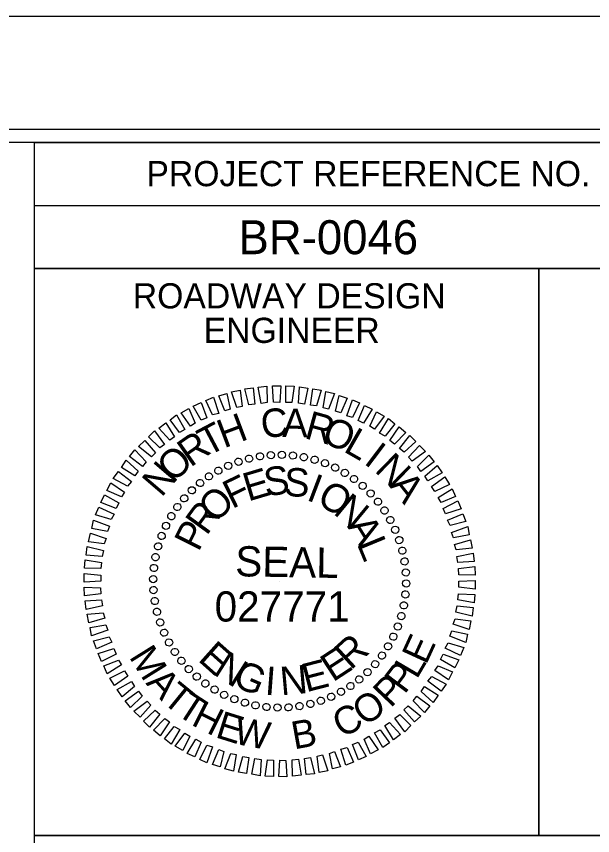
# Model space of a CAD drawing. Extents: x 1497225 to 1499181, y 579958 to 582278.
# Drawn here: x 1498688.6 to 1498802.9, y 582115.4 to 582278 of the extents above; entities that cross this region are included whole.
import ezdxf

# ---------------------------------------------------------------- set-up
doc = ezdxf.new("R2010")
doc.units = 0
for name, color, linetype in [('Sheet Cutting Line CELL', 7, 'Continuous'), ('Sheet Data Field CELL', 7, 'Continuous'), ('Sheet Plot Border Inside CELL', 7, 'Continuous'), ('Sheet Plot Border Outside CELL', 7, 'Continuous'), ('Sheet Professional Seal CELL', 7, 'Continuous'), ('Sheet Sticker Exception Certification CELL', 7, 'Continuous'), ('Sheet Typical CELL', 7, 'Continuous')]:
    doc.layers.add(name, color=color, linetype=linetype)

msp = doc.modelspace()

# ---------------------------------------------------------------- linework, layer by layer
at = {"layer": 'Sheet Cutting Line CELL'}
msp.add_line((1498909.23, 582277.96), (1497225.23, 582277.96), dxfattribs=at)
at = {"layer": 'Sheet Plot Border Inside CELL'}
msp.add_lwpolyline([(1498904.73, 582255.51), (1497238.23, 582255.51), (1497238.23, 581200.41), (1498904.73, 581200.41)], close=True, dxfattribs=at)
at = {"layer": 'Sheet Plot Border Outside CELL'}
msp.add_lwpolyline([(1498909.23, 582277.96), (1497225.23, 582277.96), (1497225.23, 581177.96), (1498909.23, 581177.96)], close=True, dxfattribs=at)
at = {"layer": 'Sheet Professional Seal CELL'}
for p, q in [((1498736.91, 582190.62), (1498736.91, 582190.62)), ((1498739.06, 582190.92), (1498739.06, 582190.92)), ((1498741.26, 582190.97), (1498741.26, 582190.97)), ((1498743.46, 582190.82), (1498743.46, 582190.82)), ((1498745.61, 582190.47), (1498745.61, 582190.47)), ((1498730.61, 582188.82), (1498730.61, 582188.82)), ((1498732.61, 582189.62), (1498732.61, 582189.62)), ((1498734.71, 582190.22), (1498734.71, 582190.22)), ((1498747.71, 582190.02), (1498747.71, 582190.02)), ((1498749.81, 582189.32), (1498749.81, 582189.32)), ((1498728.66, 582187.82), (1498728.66, 582187.82)), ((1498751.81, 582188.42), (1498751.81, 582188.42)), ((1498753.76, 582187.42), (1498753.76, 582187.42)), ((1498726.76, 582186.67), (1498726.76, 582186.67)), ((1498755.56, 582186.17), (1498755.56, 582186.17)), ((1498723.36, 582183.92), (1498723.36, 582183.92)), ((1498725.01, 582185.42), (1498725.01, 582185.42)), ((1498757.31, 582184.82), (1498757.31, 582184.82)), ((1498721.86, 582182.37), (1498721.86, 582182.37)), ((1498758.86, 582183.32), (1498758.86, 582183.32)), ((1498720.51, 582180.62), (1498720.51, 582180.62)), ((1498760.36, 582181.67), (1498760.36, 582181.67)), ((1498761.61, 582179.92), (1498761.61, 582179.92)), ((1498719.26, 582178.82), (1498719.26, 582178.82)), ((1498762.76, 582178.02), (1498762.76, 582178.02)), ((1498718.26, 582176.87), (1498718.26, 582176.87)), ((1498763.76, 582176.07), (1498763.76, 582176.07)), ((1498717.36, 582174.87), (1498717.36, 582174.87)), ((1498716.66, 582172.77), (1498716.66, 582172.77)), ((1498764.56, 582174.07), (1498764.56, 582174.07)), ((1498765.16, 582171.97), (1498765.16, 582171.97)), ((1498716.21, 582170.67), (1498716.21, 582170.67)), ((1498765.56, 582169.77), (1498765.56, 582169.77)), ((1498715.86, 582168.52), (1498715.86, 582168.52)), ((1498765.86, 582167.62), (1498765.86, 582167.62)), ((1498715.71, 582166.32), (1498715.71, 582166.32)), ((1498740.81, 582165.87), (1498740.81, 582165.87)), ((1498765.91, 582165.42), (1498765.91, 582165.42)), ((1498715.76, 582164.12), (1498715.76, 582164.12)), ((1498765.76, 582163.22), (1498765.76, 582163.22)), ((1498716.06, 582161.97), (1498716.06, 582161.97)), ((1498765.41, 582161.07), (1498765.41, 582161.07)), ((1498716.46, 582159.77), (1498716.46, 582159.77)), ((1498764.96, 582158.97), (1498764.96, 582158.97)), ((1498717.06, 582157.67), (1498717.06, 582157.67)), ((1498764.26, 582156.87), (1498764.26, 582156.87)), ((1498717.86, 582155.67), (1498717.86, 582155.67)), ((1498763.36, 582154.87), (1498763.36, 582154.87)), ((1498718.86, 582153.72), (1498718.86, 582153.72)), ((1498720.01, 582151.82), (1498720.01, 582151.82)), ((1498762.36, 582152.92), (1498762.36, 582152.92)), ((1498721.26, 582150.07), (1498721.26, 582150.07)), ((1498761.11, 582151.12), (1498761.11, 582151.12)), ((1498722.76, 582148.42), (1498722.76, 582148.42)), ((1498759.76, 582149.37), (1498759.76, 582149.37)), ((1498724.31, 582146.92), (1498724.31, 582146.92)), ((1498758.26, 582147.82), (1498758.26, 582147.82)), ((1498726.06, 582145.57), (1498726.06, 582145.57)), ((1498754.86, 582145.07), (1498754.86, 582145.07)), ((1498756.61, 582146.32), (1498756.61, 582146.32)), ((1498727.86, 582144.32), (1498727.86, 582144.32)), ((1498729.81, 582143.32), (1498729.81, 582143.32)), ((1498752.96, 582143.92), (1498752.96, 582143.92)), ((1498731.81, 582142.42), (1498731.81, 582142.42)), ((1498733.91, 582141.72), (1498733.91, 582141.72)), ((1498749.01, 582142.12), (1498749.01, 582142.12)), ((1498751.01, 582142.92), (1498751.01, 582142.92)), ((1498736.01, 582141.27), (1498736.01, 582141.27)), ((1498738.16, 582140.92), (1498738.16, 582140.92)), ((1498740.36, 582140.77), (1498740.36, 582140.77)), ((1498742.56, 582140.82), (1498742.56, 582140.82)), ((1498744.71, 582141.12), (1498744.71, 582141.12)), ((1498746.91, 582141.52), (1498746.91, 582141.52))]:
    msp.add_line(p, q, dxfattribs=at)
for points in [[(1498732.31, 582200.32), (1498731.26, 582203.47), (1498732.96, 582203.82), (1498733.36, 582200.57)], [(1498734.71, 582200.87), (1498733.91, 582204.07), (1498735.56, 582204.22), (1498735.91, 582201.02)], [(1498737.11, 582201.17), (1498736.56, 582204.37), (1498738.26, 582204.57), (1498738.31, 582201.32)], [(1498739.61, 582201.42), (1498739.36, 582204.67), (1498741.01, 582204.62), (1498740.81, 582201.37)], [(1498742.01, 582201.37), (1498742.01, 582204.62), (1498743.66, 582204.57), (1498743.21, 582201.32)], [(1498744.51, 582201.22), (1498744.71, 582204.47), (1498746.36, 582204.17), (1498745.71, 582201.02)], [(1498746.91, 582200.82), (1498747.36, 582204.02), (1498749.01, 582203.77), (1498748.11, 582200.67)], [(1498749.46, 582200.27), (1498749.96, 582203.52), (1498751.66, 582203.12), (1498750.51, 582200.02)], [(1498727.46, 582198.87), (1498726.16, 582201.77), (1498727.66, 582202.37), (1498728.71, 582199.17)], [(1498729.91, 582199.67), (1498728.76, 582202.67), (1498730.31, 582203.12), (1498730.96, 582200.02)], [(1498751.86, 582199.62), (1498752.61, 582202.72), (1498754.16, 582202.22), (1498752.91, 582199.27)], [(1498754.11, 582198.72), (1498755.26, 582201.87), (1498756.66, 582201.27), (1498755.26, 582198.37)], [(1498723.11, 582196.62), (1498721.26, 582199.32), (1498722.81, 582200.12), (1498724.06, 582197.22)], [(1498725.26, 582197.82), (1498723.66, 582200.62), (1498725.21, 582201.32), (1498726.36, 582198.27)], [(1498756.36, 582197.77), (1498757.61, 582200.72), (1498759.16, 582200.02), (1498757.46, 582197.22)], [(1498720.91, 582195.37), (1498719.06, 582197.92), (1498720.36, 582198.87), (1498722.01, 582195.97)], [(1498758.66, 582196.62), (1498760.01, 582199.47), (1498761.51, 582198.62), (1498759.61, 582196.02)], [(1498719.01, 582193.87), (1498716.86, 582196.27), (1498718.21, 582197.32), (1498719.96, 582194.52)], [(1498760.61, 582195.27), (1498762.36, 582198.17), (1498763.66, 582197.12), (1498761.71, 582194.67)], [(1498717.01, 582192.32), (1498714.81, 582194.52), (1498716.01, 582195.72), (1498717.96, 582193.02)], [(1498762.66, 582193.77), (1498764.51, 582196.52), (1498765.81, 582195.42), (1498763.61, 582193.07)], [(1498715.36, 582190.57), (1498712.81, 582192.62), (1498714.06, 582193.77), (1498716.16, 582191.37)], [(1498764.56, 582192.22), (1498766.61, 582194.82), (1498767.81, 582193.62), (1498765.51, 582191.47)], [(1498766.36, 582190.47), (1498768.51, 582192.82), (1498769.71, 582191.62), (1498767.11, 582189.67)], [(1498713.61, 582188.67), (1498711.01, 582190.62), (1498712.11, 582191.92), (1498714.31, 582189.57)], [(1498768.11, 582188.67), (1498770.41, 582190.92), (1498771.46, 582189.57), (1498768.81, 582187.67)], [(1498712.11, 582186.77), (1498709.41, 582188.47), (1498710.36, 582189.92), (1498712.76, 582187.72)], [(1498769.61, 582186.72), (1498772.06, 582188.82), (1498773.01, 582187.37), (1498770.21, 582185.77)], [(1498710.61, 582184.77), (1498707.81, 582186.27), (1498708.81, 582187.67), (1498711.41, 582185.67)], [(1498770.91, 582184.67), (1498773.56, 582186.57), (1498774.51, 582185.07), (1498771.61, 582183.67)], [(1498709.41, 582182.62), (1498706.56, 582183.87), (1498707.31, 582185.42), (1498710.01, 582183.57)], [(1498772.21, 582182.47), (1498775.01, 582184.22), (1498775.66, 582182.67), (1498772.81, 582181.52)], [(1498708.41, 582180.32), (1498705.31, 582181.47), (1498706.06, 582183.02), (1498708.91, 582181.42)], [(1498773.21, 582180.32), (1498776.16, 582181.82), (1498776.81, 582180.22), (1498773.71, 582179.22)], [(1498707.41, 582178.12), (1498704.31, 582179.02), (1498704.96, 582180.57), (1498707.96, 582179.17)], [(1498774.11, 582177.97), (1498777.16, 582179.27), (1498777.71, 582177.72), (1498774.61, 582176.92)], [(1498706.66, 582175.72), (1498703.56, 582176.37), (1498703.91, 582178.02), (1498707.06, 582176.77)], [(1498774.91, 582175.57), (1498778.11, 582176.72), (1498778.41, 582175.07), (1498775.26, 582174.52)], [(1498706.01, 582173.32), (1498702.91, 582173.72), (1498703.26, 582175.42), (1498706.41, 582174.37)], [(1498775.51, 582173.17), (1498778.66, 582174.12), (1498778.96, 582172.42), (1498775.81, 582172.12)], [(1498705.61, 582170.77), (1498702.41, 582171.07), (1498702.61, 582172.77), (1498705.86, 582171.97)], [(1498775.96, 582170.77), (1498779.21, 582171.47), (1498779.36, 582169.77), (1498776.16, 582169.57)], [(1498705.36, 582168.37), (1498702.11, 582168.47), (1498702.21, 582170.12), (1498705.46, 582169.57)], [(1498776.26, 582168.37), (1498779.51, 582168.77), (1498779.61, 582167.07), (1498776.36, 582167.17)], [(1498705.31, 582165.87), (1498702.06, 582165.72), (1498702.06, 582167.42), (1498705.31, 582167.07)], [(1498776.31, 582165.87), (1498779.56, 582166.02), (1498779.56, 582164.32), (1498776.31, 582164.67)], [(1498705.36, 582163.37), (1498702.11, 582162.97), (1498702.01, 582164.67), (1498705.26, 582164.57)], [(1498776.26, 582163.37), (1498779.51, 582163.27), (1498779.41, 582161.62), (1498776.16, 582162.17)], [(1498705.66, 582160.97), (1498702.41, 582160.27), (1498702.26, 582161.97), (1498705.46, 582162.17)], [(1498706.11, 582158.57), (1498702.96, 582157.62), (1498702.66, 582159.32), (1498705.81, 582159.62)], [(1498776.01, 582160.97), (1498779.21, 582160.67), (1498779.01, 582158.97), (1498775.76, 582159.77)], [(1498775.61, 582158.42), (1498778.71, 582158.02), (1498778.36, 582156.32), (1498775.21, 582157.37)], [(1498706.71, 582156.17), (1498703.51, 582155.02), (1498703.21, 582156.67), (1498706.36, 582157.22)], [(1498707.51, 582153.77), (1498704.46, 582152.47), (1498703.91, 582154.02), (1498707.01, 582154.82)], [(1498774.96, 582156.02), (1498778.06, 582155.37), (1498777.71, 582153.72), (1498774.56, 582154.97)], [(1498774.21, 582153.62), (1498777.31, 582152.72), (1498776.66, 582151.17), (1498773.66, 582152.57)], [(1498708.41, 582151.42), (1498705.46, 582149.92), (1498704.81, 582151.52), (1498707.91, 582152.52)], [(1498773.21, 582151.42), (1498776.31, 582150.27), (1498775.56, 582148.72), (1498772.71, 582150.32)], [(1498709.41, 582149.27), (1498706.61, 582147.52), (1498705.96, 582149.07), (1498708.81, 582150.22)], [(1498710.71, 582147.07), (1498708.06, 582145.17), (1498707.11, 582146.67), (1498710.01, 582148.07)], [(1498772.21, 582149.12), (1498775.06, 582147.87), (1498774.31, 582146.32), (1498771.61, 582148.17)], [(1498771.01, 582146.97), (1498773.81, 582145.47), (1498772.81, 582144.07), (1498770.21, 582146.07)], [(1498712.01, 582145.02), (1498709.56, 582142.92), (1498708.61, 582144.37), (1498711.41, 582145.97)], [(1498769.51, 582144.97), (1498772.21, 582143.27), (1498771.26, 582141.82), (1498768.86, 582144.02)], [(1498713.51, 582143.07), (1498711.21, 582140.82), (1498710.16, 582142.17), (1498712.81, 582144.07)], [(1498715.26, 582141.27), (1498713.11, 582138.92), (1498711.91, 582140.12), (1498714.51, 582142.07)], [(1498768.01, 582143.07), (1498770.61, 582141.12), (1498769.51, 582139.82), (1498767.31, 582142.17)], [(1498717.06, 582139.52), (1498715.01, 582136.92), (1498713.81, 582138.12), (1498716.11, 582140.27)], [(1498766.26, 582141.17), (1498768.81, 582139.12), (1498767.56, 582137.97), (1498765.46, 582140.37)], [(1498718.96, 582137.97), (1498717.11, 582135.22), (1498715.81, 582136.32), (1498718.01, 582138.67)], [(1498764.61, 582139.42), (1498766.81, 582137.22), (1498765.61, 582136.02), (1498763.66, 582138.72)], [(1498721.01, 582136.47), (1498719.26, 582133.57), (1498717.96, 582134.62), (1498719.91, 582137.07)], [(1498762.61, 582137.87), (1498764.76, 582135.47), (1498763.41, 582134.42), (1498761.66, 582137.22)], [(1498722.96, 582135.12), (1498721.61, 582132.27), (1498720.11, 582133.12), (1498722.01, 582135.72)], [(1498758.51, 582135.12), (1498760.36, 582132.42), (1498758.81, 582131.62), (1498757.56, 582134.52)], [(1498760.71, 582136.37), (1498762.56, 582133.82), (1498761.26, 582132.87), (1498759.61, 582135.77)], [(1498725.26, 582133.97), (1498724.01, 582131.02), (1498722.46, 582131.72), (1498724.16, 582134.52)], [(1498756.36, 582133.92), (1498757.96, 582131.12), (1498756.41, 582130.42), (1498755.26, 582133.47)], [(1498727.51, 582133.02), (1498726.36, 582129.87), (1498724.96, 582130.47), (1498726.36, 582133.37)], [(1498729.76, 582132.12), (1498729.01, 582129.02), (1498727.46, 582129.52), (1498728.71, 582132.47)], [(1498751.71, 582132.07), (1498752.86, 582129.07), (1498751.31, 582128.62), (1498750.66, 582131.72)], [(1498754.16, 582132.87), (1498755.46, 582129.97), (1498753.96, 582129.37), (1498752.91, 582132.57)], [(1498732.16, 582131.47), (1498731.66, 582128.22), (1498729.96, 582128.62), (1498731.11, 582131.72)], [(1498734.71, 582130.92), (1498734.26, 582127.72), (1498732.61, 582127.97), (1498733.51, 582131.07)], [(1498737.11, 582130.52), (1498736.91, 582127.27), (1498735.26, 582127.57), (1498735.91, 582130.72)], [(1498739.61, 582130.37), (1498739.61, 582127.12), (1498737.96, 582127.17), (1498738.41, 582130.42)], [(1498742.01, 582130.32), (1498742.26, 582127.07), (1498740.61, 582127.12), (1498740.81, 582130.37)], [(1498744.51, 582130.57), (1498745.06, 582127.37), (1498743.36, 582127.17), (1498743.31, 582130.42)], [(1498746.91, 582130.87), (1498747.71, 582127.67), (1498746.06, 582127.52), (1498745.71, 582130.72)], [(1498749.31, 582131.42), (1498750.36, 582128.27), (1498748.66, 582127.92), (1498748.26, 582131.17)]]:
    msp.add_lwpolyline(points, close=True, dxfattribs=at)
for centre, major_axis in [((1498732.64, 582189.59), (-0.234, 0.681)), ((1498734.74, 582190.21), (-0.174, 0.699)), ((1498736.89, 582190.65), (-0.113, 0.711)), ((1498739.06, 582190.89), (-0.05, 0.718)), ((1498741.25, 582190.95), (0.013, 0.72)), ((1498743.43, 582190.82), (0.075, 0.716)), ((1498745.59, 582190.49), (0.137, 0.707)), ((1498747.72, 582189.98), (0.198, 0.692)), ((1498730.61, 582188.79), (-0.293, 0.658)), ((1498749.8, 582189.29), (0.258, 0.672)), ((1498751.8, 582188.42), (0.316, 0.647)), ((1498726.78, 582186.67), (-0.403, 0.597)), ((1498728.65, 582187.81), (-0.349, 0.63)), ((1498753.73, 582187.37), (0.371, 0.617)), ((1498725.03, 582185.36), (-0.453, 0.56)), ((1498755.55, 582186.16), (0.423, 0.582)), ((1498757.26, 582184.8), (0.472, 0.543)), ((1498723.39, 582183.92), (-0.5, 0.518)), ((1498758.85, 582183.3), (0.518, 0.5)), ((1498721.88, 582182.33), (-0.543, 0.472)), ((1498760.3, 582181.66), (0.56, 0.453)), ((1498720.52, 582180.62), (-0.582, 0.423)), ((1498761.6, 582179.9), (0.597, 0.403)), ((1498719.31, 582178.79), (-0.617, 0.371)), ((1498718.27, 582176.87), (-0.647, 0.316)), ((1498762.74, 582178.03), (0.63, 0.349)), ((1498763.72, 582176.08), (0.658, 0.293)), ((1498717.4, 582174.86), (-0.672, 0.258)), ((1498764.52, 582174.04), (0.681, 0.234)), ((1498716.7, 582172.79), (-0.692, 0.198)), ((1498765.14, 582171.94), (0.699, 0.174)), ((1498716.19, 582170.66), (-0.707, 0.137)), ((1498715.87, 582168.5), (-0.716, 0.075)), ((1498765.58, 582169.8), (0.711, 0.113)), ((1498765.83, 582167.62), (0.718, 0.05)), ((1498715.73, 582166.31), (-0.72, 0.013)), ((1498765.89, 582165.44), (0.72, -0.013)), ((1498715.79, 582164.12), (-0.718, -0.05)), ((1498716.04, 582161.95), (-0.711, -0.113)), ((1498765.75, 582163.25), (0.716, -0.075)), ((1498765.43, 582161.09), (0.707, -0.137)), ((1498716.47, 582159.81), (-0.699, -0.174)), ((1498764.92, 582158.96), (0.692, -0.198)), ((1498717.1, 582157.71), (-0.681, -0.234)), ((1498717.9, 582155.67), (-0.658, -0.293)), ((1498764.22, 582156.89), (0.672, -0.258)), ((1498763.35, 582154.88), (0.647, -0.316)), ((1498718.87, 582153.72), (-0.63, -0.349)), ((1498762.31, 582152.96), (0.617, -0.371)), ((1498720.02, 582151.85), (-0.597, -0.403)), ((1498761.1, 582151.13), (0.582, -0.423)), ((1498721.32, 582150.09), (-0.56, -0.453)), ((1498759.74, 582149.42), (0.543, -0.472)), ((1498722.77, 582148.45), (-0.518, -0.5)), ((1498758.23, 582147.83), (0.5, -0.518)), ((1498724.36, 582146.95), (-0.472, -0.543)), ((1498756.59, 582146.38), (0.453, -0.56)), ((1498726.07, 582145.58), (-0.423, -0.582)), ((1498727.89, 582144.38), (-0.371, -0.617)), ((1498754.83, 582145.08), (0.403, -0.597)), ((1498729.81, 582143.33), (-0.316, -0.647)), ((1498731.82, 582142.46), (-0.258, -0.672)), ((1498751.01, 582142.96), (0.293, -0.658)), ((1498752.97, 582143.94), (0.349, -0.63)), ((1498733.9, 582141.77), (-0.198, -0.692)), ((1498736.02, 582141.25), (-0.137, -0.707)), ((1498738.19, 582140.93), (-0.075, -0.716)), ((1498742.56, 582140.86), (0.05, -0.718)), ((1498744.73, 582141.1), (0.113, -0.711)), ((1498746.88, 582141.54), (0.174, -0.699)), ((1498748.97, 582142.16), (0.234, -0.681)), ((1498740.37, 582140.8), (-0.013, -0.72))]:
    msp.add_ellipse(centre, major_axis=major_axis, ratio=0.999708, dxfattribs=at)
at = {"layer": 'Sheet Sticker Exception Certification CELL'}
for p, q in [((1498692.18, 582091.91), (1498692.18, 582115.41)), ((1498692.18, 582115.41), (1498892.22, 582115.41))]:
    msp.add_line(p, q, dxfattribs=at)
at = {"layer": 'Sheet Typical CELL'}
for p, q in [((1498692.18, 582240.41), (1498892.23, 582240.41)), ((1498792.23, 582227.91), (1498792.23, 582115.46))]:
    msp.add_line(p, q, dxfattribs=at)
for points in [[(1498892.23, 582252.96), (1497392.23, 582252.96), (1497392.23, 581202.96), (1498892.23, 581202.96)], [(1498692.18, 582252.96), (1498892.23, 582252.96), (1498892.23, 582227.91), (1498692.18, 582227.91)], [(1498692.18, 582227.91), (1498792.23, 582227.91), (1498792.23, 582115.41), (1498692.18, 582115.41)], [(1498792.23, 582227.91), (1498892.23, 582227.91), (1498892.23, 582115.41), (1498792.23, 582115.41)]]:
    msp.add_lwpolyline(points, close=True, dxfattribs=at)

# ---------------------------------------------------------------- texts
at = {"layer": 'Sheet Data Field CELL'}
msp.add_text('BR-0046', height=6.75, dxfattribs=at).set_placement((1498732.64, 582230.76))
at = {"layer": 'Sheet Professional Seal CELL'}
for s, height, rotation, p in [('C', 5.64, 6.2199, (1498737.36, 582194.22)), ('A', 5.64, 359.0203, (1498741.31, 582194.52)), ('H', 5.64, 20.6195, (1498729.76, 582192.22)), ('R', 5.64, 344.6211, (1498745.51, 582194.32)), ('T', 5.64, 27.8198, (1498726.51, 582190.57)), ('O', 5.64, 337.4212, (1498748.86, 582193.57)), ('R', 5.64, 35.0205, (1498723.11, 582188.37)), ('L', 5.64, 330.2209, (1498753.26, 582191.72)), ('O', 5.64, 42.2217, (1498719.66, 582185.27)), ('I', 5.64, 323.0201, (1498757.31, 582189.32)), ('N', 5.64, 315.8189, (1498759.46, 582187.77)), ('N', 5.64, 49.4235, (1498717.36, 582182.37)), ('S', 5.64, 7.2556, (1498738.01, 582182.72)), ('F', 5.64, 25.967, (1498731.36, 582180.17)), ('E', 5.64, 16.6111, (1498734.56, 582181.67)), ('S', 5.64, 357.9004, (1498741.61, 582182.77)), ('I', 5.64, 339.1896, (1498745.91, 582182.07)), ('O', 5.64, 329.8335, (1498747.91, 582181.37)), ('A', 5.64, 308.6172, (1498762.41, 582184.82)), ('O', 5.64, 44.6812, (1498728.06, 582177.22)), ('N', 5.64, 320.4766, (1498751.26, 582179.37)), ('R', 5.64, 54.0397, (1498726.31, 582174.77)), ('P', 5.64, 63.3989, (1498724.71, 582171.57)), ('A', 5.64, 301.7603, (1498754.11, 582176.77)), ('L', 5.64, 292.4008, (1498756.06, 582173.32)), ('SEAL', 5.998, 359, (1498731.96, 582166.87)), ('R', 5.64, 42.4814, (1498754.91, 582148.12)), ('E', 5.5, 65.3458, (1498769.84, 582149.13)), ('M', 5.5, 301.8863, (1498710.84, 582150.89)), ('E', 5.64, 318.2769, (1498724.41, 582150.22)), ('E', 5.64, 33.1241, (1498751.36, 582145.77)), ('N', 5.64, 327.634, (1498727.41, 582147.52)), ('G', 5.64, 336.9902, (1498731.21, 582145.27)), ('E', 5.64, 14.4118, (1498746.06, 582143.82)), ('L', 5.5, 59.5356, (1498767.99, 582146.28)), ('I', 5.64, 355.7012, (1498737.76, 582143.37)), ('N', 5.64, 5.0564, (1498741.11, 582143.22)), ('P', 5.5, 52.9527, (1498765.57, 582143.29)), ('A', 5.5, 312.5622, (1498714.13, 582145.6)), ('P', 5.5, 46.3697, (1498762.81, 582140.6)), ('T', 5.5, 320.748, (1498717.29, 582142)), ('T', 5.5, 327.0447, (1498720.05, 582139.57)), ('O', 5.5, 35.6652, (1498757.74, 582136.96)), ('H', 5.5, 333.3415, (1498723.06, 582137.45)), ('E', 5.5, 342.5863, (1498727.86, 582134.97)), ('C', 5.5, 26.7925, (1498753.07, 582134.69)), ('W', 5.5, 349.1693, (1498731.49, 582133.69)), ('B', 5.5, 10.2205, (1498743.67, 582132.49))]:
    msp.add_text(s, height=height, rotation=rotation, dxfattribs=at).set_placement(p)
msp.add_text('027771', height=5.998, dxfattribs=at).set_placement((1498727.91, 582157.87))
at = {"layer": 'Sheet Typical CELL'}
for s, height, p in [('PROJECT REFERENCE NO.', 5.0001, (1498714.38, 582244.26)), ('ROADWAY DESIGN', 5.0001, (1498711.68, 582220.01)), ('ENGINEER', 5, (1498725.73, 582213.16))]:
    msp.add_text(s, height=height, dxfattribs=at).set_placement(p)

doc.saveas('drawing.dxf')
